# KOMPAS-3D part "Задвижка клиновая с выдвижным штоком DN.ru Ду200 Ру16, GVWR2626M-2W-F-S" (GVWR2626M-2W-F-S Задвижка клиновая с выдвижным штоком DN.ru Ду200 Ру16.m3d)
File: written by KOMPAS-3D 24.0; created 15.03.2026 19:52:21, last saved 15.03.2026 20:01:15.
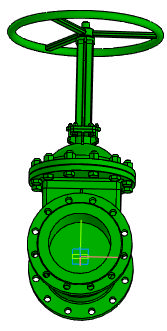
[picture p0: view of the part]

Document properties: Автор: R2D2; Полное имя файла: GVWR2626M-2W-F-S Задвижка клиновая с выдвижным штоком DN.ru Ду200 Ру16.cdw

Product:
- Part/product: Задвижка клиновая с выдвижным штоком DN.ru Ду200 Ру16  | designation GVWR2626M-2W-F-S
    Масса: 108
    Раздел спецификации: Прочие изделия
    Форматы листов документа: A2
    Примечание: D040-10505

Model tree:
1. Операция без истории:1

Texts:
  GVWR2626M-2W-F-S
